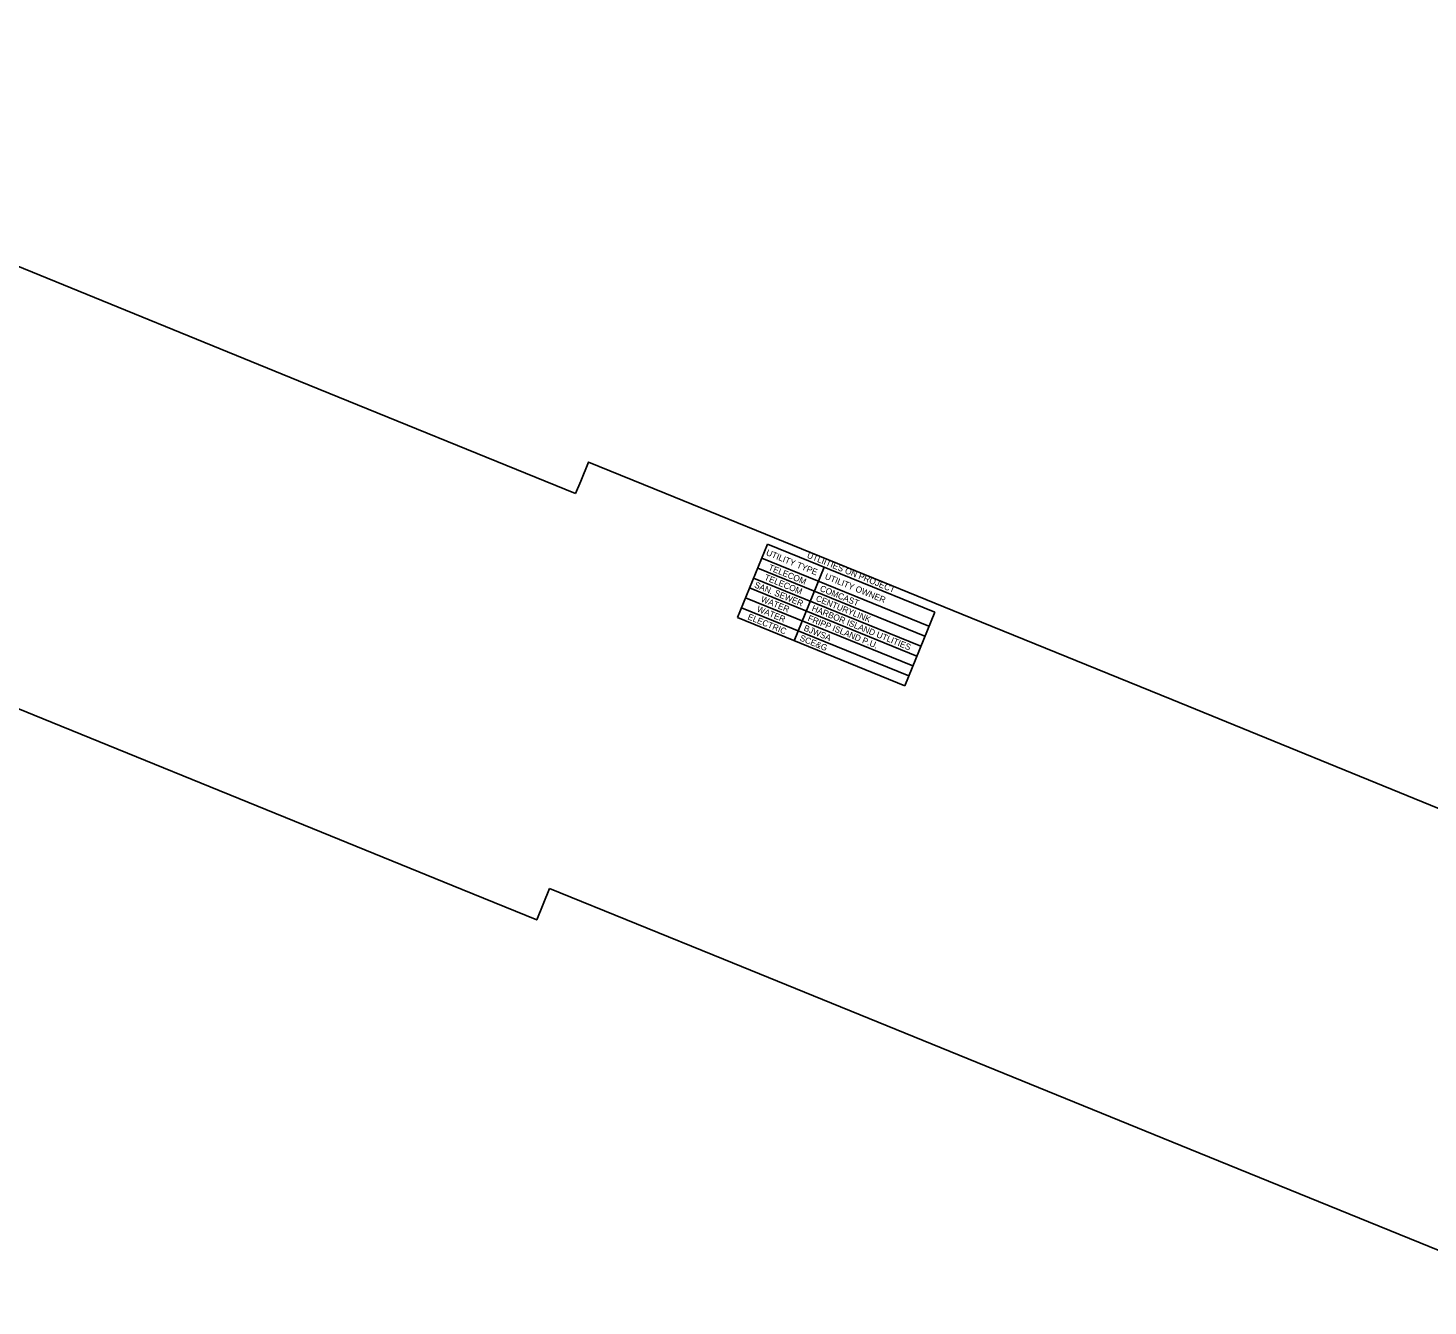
# Model space of a CAD drawing. Extents: x 2162629 to 2176228, y 202467 to 210920.
# Drawn here: x 2167729 to 2169428, y 207727 to 209279 of the extents above; entities that cross this region are included whole.
import ezdxf

# ---------------------------------------------------------------- set-up
doc = ezdxf.new("R2010")
doc.units = 0
doc.layers.add('RD_SHT_ShtClip', color=7, linetype='Continuous')
doc.layers.add('RD_SHT_TX', color=7, linetype='Continuous')

msp = doc.modelspace()

# ---------------------------------------------------------------- linework, layer by layer
at = {"layer": 'RD_SHT_ShtClip'}
for points in [[(2168393.4, 208713.8), (2168057, 208850.8), (2167714, 208990.5), (2167470.1, 209089.8), (2167297, 209160.3), (2167098.3, 209241.3), (2167005.7, 209279), (2166996.2, 209255.9), (2166980.2, 209216.5)], [(2169902.8, 208045.4), (2169908.9, 208060.2), (2169923.9, 208097.2), (2169784.2, 208154.1), (2169797.4, 208186.5), (2169460.3, 208323.8), (2169117.3, 208463.5), (2168873.4, 208562.8), (2168700.4, 208633.3), (2168501.6, 208714.3), (2168409, 208752), (2168399.6, 208728.8), (2168393.4, 208713.8)], [(2167307.9, 208619), (2167466.8, 208554.3), (2167746.9, 208440.2), (2168063.2, 208311.4), (2168255.6, 208233), (2168346.2, 208196.1), (2168361.8, 208234.4)], [(2168361.8, 208234.4), (2168573.1, 208148.3), (2168870.1, 208027.3), (2169150.2, 207913.2), (2169466.6, 207784.4), (2169606.7, 207727.3)]]:
    msp.add_lwpolyline(points, dxfattribs=at)
at = {"layer": 'RD_SHT_TX'}
for p, q in [((2168626.3, 208652.4), (2168590, 208563.1)), ((2168626.3, 208652.4), (2168829.4, 208569.7)), ((2168619.4, 208635.3), (2168822.4, 208552.6)), ((2168609.6, 208611.2), (2168812.6, 208528.5)), ((2168614.5, 208623.3), (2168817.5, 208540.6)), ((2168695.1, 208624.4), (2168658.7, 208535.1)), ((2168604.7, 208599.2), (2168807.7, 208516.5)), ((2168594.9, 208575.1), (2168797.9, 208492.4)), ((2168599.8, 208587.2), (2168802.8, 208504.5)), ((2168590, 208563.1), (2168793, 208480.4)), ((2168829.4, 208569.7), (2168793, 208480.4))]:
    msp.add_line(p, q, dxfattribs=at)

# ---------------------------------------------------------------- texts
for s, p in [('UTILITY TYPE', (2168624, 208639.3)), ('TELECOM', (2168626.8, 208621.2)), ('UTLIITIES ON PROJECT', (2168673.7, 208636.1)), ('TELECOM', (2168621.9, 208609.2)), ('UTILITY OWNER', (2168695.3, 208610.3)), ('SAN. SEWER', (2168609.7, 208600.1)), ('COMCAST', (2168689.3, 208595.7)), ('WATER', (2168612.8, 208570.8)), ('WATER', (2168617.7, 208582.8)), ('HARBOR ISLAND UTLITIES', (2168679.5, 208571.7)), ('CENTURYLINK', (2168684.4, 208583.7)), ('ELECTRIC', (2168601.6, 208561.3)), ('FRIPP ISLAND P.U.', (2168674.6, 208559.6)), ('SCE&G', (2168664.8, 208535.6)), ('BJWSA', (2168669.7, 208547.6))]:
    msp.add_text(s, height=7.5, rotation=337.8388, dxfattribs=at).set_placement(p)

doc.saveas('drawing.dxf')
